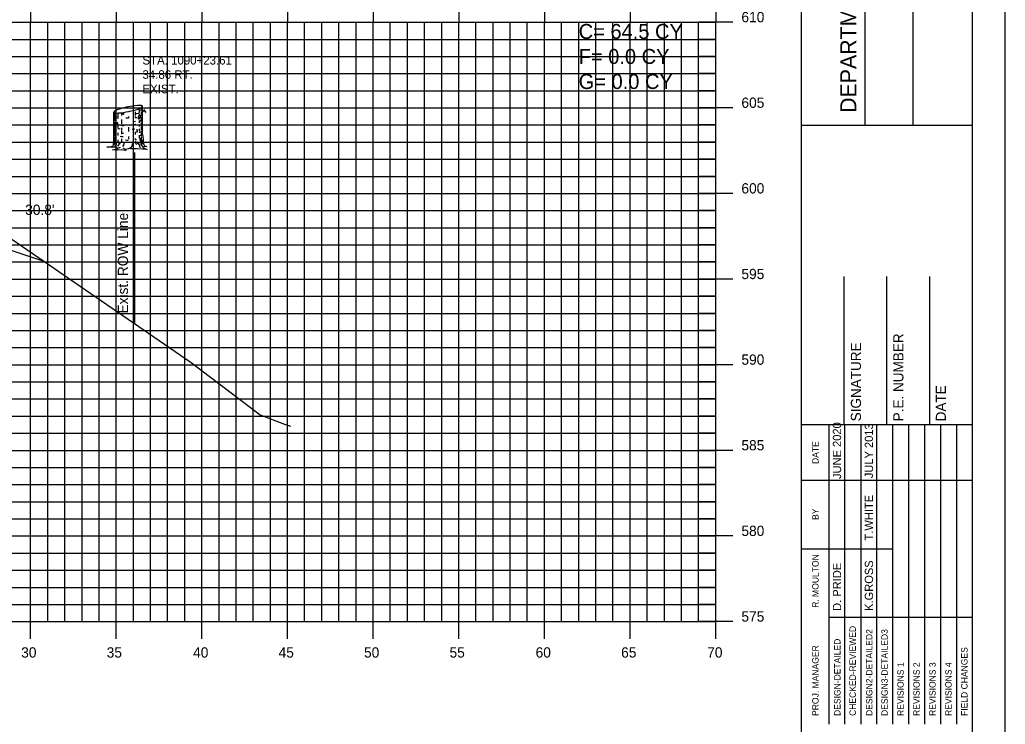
# Model space of a CAD drawing. Extents: x 1073421 to 1073591, y 779716 to 779826.
# Drawn here: x 1073533.3 to 1073590.9, y 779763.7 to 779804.9 of the extents above; entities that cross this region are included whole.
import ezdxf

# ---------------------------------------------------------------- set-up
doc = ezdxf.new("R2010")
doc.units = 0
for name, color, linetype in [('BORDER', 7, 'Continuous'), ('D_Roadway_Centerline', 7, 'Continuous'), ('D_Text_Monospaced', 7, 'Continuous'), ('D_Text_Standard', 7, 'Continuous'), ('E_ROW_Line', 7, 'Continuous'), ('H_V ANNOTATION', 7, 'Continuous'), ('M_Trees_Conifer_Pay', 7, 'Continuous'), ('MAJOR', 7, 'Continuous'), ('MINOR', 7, 'Continuous'), ('PLOT BOUNDARY', 7, 'Continuous'), ('S_Roadway_Centerline', 7, 'Continuous'), ('S_Trees_Decid_Pay', 7, 'Continuous')]:
    doc.layers.add(name, color=color, linetype=linetype)

msp = doc.modelspace()

# ---------------------------------------------------------------- linework, layer by layer
at = {"layer": 'BORDER'}
for p, q in [((1073578.959, 779718.706), (1073578.959, 779823.706)), ((1073582.688, 779798.703), (1073582.688, 779823.703)), ((1073585.483, 779798.703), (1073585.483, 779823.703)), ((1073578.96, 779798.7), (1073588.959, 779798.7)), ((1073581.459, 779781.209), (1073581.459, 779789.856)), ((1073583.959, 779781.209), (1073583.959, 779789.856)), ((1073586.459, 779781.209), (1073586.459, 779789.856)), ((1073578.959, 779781.209), (1073588.959, 779781.209))]:
    msp.add_line(p, q, dxfattribs=at)
msp.add_lwpolyline([(1073428.959, 779718.706), (1073588.959, 779718.706), (1073588.959, 779823.706), (1073428.959, 779823.706)], close=True, dxfattribs=at)
for points in [[(1073580.574, 779777.959), (1073580.574, 779781.209)], [(1073581.507, 779763.712), (1073581.507, 779781.209)], [(1073582.439, 779781.209), (1073582.439, 779763.712)], [(1073583.37, 779763.712), (1073583.37, 779781.209)], [(1073584.302, 779763.712), (1073584.302, 779781.209)], [(1073585.234, 779763.712), (1073585.234, 779781.209)], [(1073586.165, 779763.712), (1073586.165, 779781.209)], [(1073587.097, 779763.712), (1073587.097, 779781.209)], [(1073588.029, 779763.712), (1073588.029, 779781.209)], [(1073580.575, 779763.712), (1073580.575, 779780.503)], [(1073578.959, 779777.959), (1073588.959, 779777.959)], [(1073578.959, 779773.959), (1073580.575, 779773.959)], [(1073580.574, 779773.959), (1073584.301, 779773.959)], [(1073580.574, 779769.959), (1073588.959, 779769.959)]]:
    msp.add_lwpolyline(points, dxfattribs=at)
at = {"layer": 'D_Roadway_Centerline'}
msp.add_lwpolyline([(1073529.418, 779792.528), (1073534.736, 779790.755)], dxfattribs=at)
at = {"layer": 'E_ROW_Line'}
msp.add_line((1073540.047, 779787.094), (1073540.047, 779797.094), dxfattribs=at)
msp.add_line((1073540.047, 779787.094), (1073540.047, 779797.094), dxfattribs=at)
at = {"layer": 'M_Trees_Conifer_Pay'}
for p, q in [((1073538.822, 779797.738), (1073538.822, 779799.46)), ((1073540.069, 779799.466), (1073540.069, 779799.266)), ((1073540.297, 779799.662), (1073540.297, 779799.439)), ((1073540.414, 779799.723), (1073540.414, 779799.56)), ((1073540.414, 779799.493), (1073540.414, 779799.365)), ((1073540.486, 779798.148), (1073540.486, 779799.795)), ((1073538.869, 779799.423), (1073538.869, 779798.951)), ((1073538.869, 779798.887), (1073538.869, 779798.579)), ((1073538.927, 779799.411), (1073538.927, 779799.314)), ((1073538.927, 779799.239), (1073538.927, 779799.035)), ((1073538.927, 779798.978), (1073538.927, 779798.778)), ((1073539.053, 779799.404), (1073539.053, 779799.171)), ((1073539.053, 779799.131), (1073539.053, 779799.056)), ((1073539.273, 779799.424), (1073539.273, 779799.256)), ((1073539.273, 779799.019), (1073539.273, 779798.782)), ((1073539.678, 779799.192), (1073539.678, 779799.097)), ((1073540.069, 779799.209), (1073540.069, 779799.12)), ((1073540.297, 779799.35), (1073540.297, 779799.303)), ((1073540.297, 779798.968), (1073540.297, 779798.836)), ((1073540.354, 779799.167), (1073540.303, 779799.108)), ((1073540.414, 779799.178), (1073540.414, 779798.842)), ((1073538.869, 779798.531), (1073538.869, 779798.039)), ((1073538.927, 779798.731), (1073538.927, 779798.395)), ((1073538.927, 779798.342), (1073538.927, 779798.206)), ((1073539.053, 779798.653), (1073539.053, 779798.514)), ((1073539.273, 779798.537), (1073539.273, 779798.385)), ((1073539.273, 779798.342), (1073539.273, 779798.169)), ((1073539.678, 779798.579), (1073539.678, 779798.505)), ((1073539.678, 779798.48), (1073539.678, 779798.331)), ((1073540.069, 779798.772), (1073540.069, 779798.667)), ((1073540.069, 779798.301), (1073540.069, 779798.154)), ((1073540.297, 779798.725), (1073540.297, 779798.615)), ((1073540.297, 779798.48), (1073540.297, 779798.338)), ((1073540.414, 779798.805), (1073540.414, 779798.642)), ((1073540.414, 779798.595), (1073540.414, 779798.379)), ((1073540.414, 779798.348), (1073540.414, 779798.274)), ((1073538.869, 779797.986), (1073538.869, 779797.738)), ((1073538.927, 779798.107), (1073538.927, 779797.728)), ((1073539.053, 779798.243), (1073539.053, 779798.101)), ((1073539.053, 779797.839), (1073539.053, 779797.745)), ((1073539.273, 779797.891), (1073539.273, 779797.738)), ((1073539.678, 779798.039), (1073539.678, 779797.886)), ((1073540.069, 779797.922), (1073540.069, 779797.833)), ((1073540.297, 779798.111), (1073540.297, 779797.938)), ((1073540.414, 779798.233), (1073540.414, 779798.06)), ((1073539.053, 779797.345), (1073539.216, 779797.409)), ((1073539.49, 779797.281), (1073539.364, 779797.345))]:
    msp.add_line(p, q, dxfattribs=at)
for points in [[(1073540.303, 779799.293), (1073540.34, 779799.219), (1073540.387, 779799.276), (1073540.445, 779799.344), (1073540.537, 779799.538), (1073540.601, 779799.585), (1073540.632, 779799.592)], [(1073540.317, 779799.04), (1073540.354, 779799.167), (1073540.418, 779799.283), (1073540.448, 779799.35), (1073540.517, 779799.497)], [(1073540.532, 779799.526), (1073540.607, 779799.534), (1073540.679, 779799.435)], [(1073539.001, 779798.766), (1073538.995, 779798.861), (1073539.038, 779798.838), (1073539.038, 779798.743)], [(1073540.269, 779799.256), (1073540.238, 779799.171), (1073540.235, 779799.104), (1073540.265, 779799.04)], [(1073540.14, 779798.367), (1073540.153, 779798.29), (1073540.2, 779798.301), (1073540.187, 779798.467)], [(1073540.486, 779798.148), (1073540.537, 779797.886), (1073540.553, 779797.613), (1073540.611, 779797.488), (1073540.747, 779797.457), (1073540.517, 779797.419), (1073540.517, 779797.419), (1073540.523, 779797.372), (1073540.77, 779797.278), (1073540.496, 779797.294), (1073540.14, 779797.314), (1073539.819, 779797.304), (1073539.825, 779797.386), (1073539.677, 779797.304), (1073539.49, 779797.281), (1073539.514, 779797.213), (1073539.246, 779797.257), (1073539.026, 779797.23), (1073538.733, 779797.247), (1073539.022, 779797.304), (1073539.053, 779797.345), (1073538.89, 779797.403), (1073538.653, 779797.413), (1073538.412, 779797.413), (1073538.754, 779797.471), (1073538.796, 779797.551), (1073538.822, 779797.738)], [(1073540.076, 779797.755), (1073540.086, 779797.629), (1073540.16, 779797.586)], [(1073540.313, 779797.86), (1073540.387, 779797.755), (1073540.391, 779797.582), (1073540.517, 779797.419)], [(1073540.412, 779798.006), (1073540.418, 779797.86), (1073540.465, 779797.792), (1073540.475, 779797.593)], [(1073538.87, 779797.691), (1073538.849, 779797.613), (1073538.828, 779797.518)], [(1073538.948, 779797.671), (1073538.954, 779797.555), (1073538.901, 779797.467), (1073538.89, 779797.403)], [(1073539.111, 779797.698), (1073539.111, 779797.566), (1073539.022, 779797.467)], [(1073539.337, 779797.457), (1073539.404, 779797.551), (1073539.431, 779797.691)], [(1073539.825, 779797.386), (1073539.899, 779797.528), (1073539.909, 779797.629)], [(1073540.354, 779797.366), (1073540.34, 779797.504), (1073540.265, 779797.633)]]:
    msp.add_lwpolyline(points, dxfattribs=at)
for centre, radius, start, end in [((1073540.155, 779800.109), 0.571, 284.43166, 292.41325), ((1073539.153, 779799.51), 0.571, 240, 247.05866), ((1073539.152, 779799.721), 0.571, 246.85973, 257.98457), ((1073539.654, 779803.472), 4.124, 264.6955, 266.73309), ((1073539.654, 779803.028), 4.124, 273.70524, 275.95043), ((1073539.653, 779803.239), 4.124, 275.78493, 277.05584), ((1073540.155, 779799.51), 0.571, 284.44928, 297.04285), ((1073540.453, 779799.071), 0.0334, 343.94846, 354.21506), ((1073539.653, 779802.792), 4.124, 264.08098, 266.66759), ((1073539.653, 779802.582), 4.124, 270, 270.35814), ((1073539.653, 779802.582), 4.124, 273.14934, 275.45691), ((1073540.153, 779798.828), 0.571, 285.39827, 297.18959), ((1073538.854, 779798.19), 0.0334, 163.94846, 180), ((1073539.141, 779798.636), 0.571, 241.23686, 248.02677), ((1073539.653, 779802.148), 4.124, 263.49906, 265.83975), ((1073539.653, 779802.345), 4.124, 264.71603, 266.31934), ((1073539.653, 779801.952), 4.124, 275.78493, 276.78961), ((1073540.153, 779798.435), 0.571, 288.50673, 297.27208), ((1073539.653, 779801.732), 4.124, 262.44379, 263.51202)]:
    msp.add_arc(centre, radius, start, end, dxfattribs=at)
at = {"layer": 'MAJOR'}
for p, q in [((1073533.959, 779805.708), (1073533.959, 779804.706)), ((1073538.959, 779805.708), (1073538.959, 779804.706)), ((1073543.959, 779805.708), (1073543.959, 779804.706)), ((1073548.959, 779805.708), (1073548.959, 779804.706)), ((1073553.959, 779805.708), (1073553.959, 779804.706)), ((1073558.959, 779805.708), (1073558.959, 779804.706)), ((1073563.959, 779805.708), (1073563.959, 779804.706)), ((1073568.959, 779805.708), (1073568.959, 779804.706)), ((1073573.959, 779805.708), (1073573.959, 779804.706)), ((1073433.959, 779804.706), (1073573.959, 779804.706)), ((1073433.959, 779804.706), (1073573.959, 779804.706)), ((1073533.959, 779769.706), (1073533.959, 779804.706)), ((1073538.959, 779769.706), (1073538.959, 779804.706)), ((1073543.959, 779769.706), (1073543.959, 779804.706)), ((1073548.959, 779769.706), (1073548.959, 779804.706)), ((1073553.959, 779769.706), (1073553.959, 779804.706)), ((1073558.959, 779769.706), (1073558.959, 779804.706)), ((1073563.959, 779769.706), (1073563.959, 779804.706)), ((1073568.959, 779769.706), (1073568.959, 779804.706)), ((1073574.961, 779804.706), (1073572.957, 779804.706)), ((1073573.959, 779769.706), (1073573.959, 779804.706)), ((1073573.959, 779769.706), (1073573.959, 779804.706)), ((1073433.959, 779799.706), (1073573.959, 779799.706)), ((1073574.961, 779799.706), (1073572.957, 779799.706)), ((1073433.959, 779794.706), (1073573.959, 779794.706)), ((1073574.961, 779794.706), (1073572.957, 779794.706)), ((1073433.959, 779789.706), (1073573.959, 779789.706)), ((1073574.961, 779789.706), (1073572.957, 779789.706)), ((1073433.959, 779784.706), (1073573.959, 779784.706)), ((1073574.961, 779784.706), (1073572.957, 779784.706)), ((1073433.959, 779779.706), (1073573.959, 779779.706)), ((1073574.961, 779779.706), (1073572.957, 779779.706)), ((1073433.959, 779774.706), (1073573.959, 779774.706)), ((1073574.961, 779774.706), (1073572.957, 779774.706)), ((1073433.959, 779769.706), (1073573.959, 779769.706)), ((1073433.959, 779769.706), (1073573.959, 779769.706)), ((1073533.959, 779768.704), (1073533.959, 779769.706)), ((1073538.959, 779768.704), (1073538.959, 779769.706)), ((1073543.959, 779768.704), (1073543.959, 779769.706)), ((1073548.959, 779768.704), (1073548.959, 779769.706)), ((1073553.959, 779768.704), (1073553.959, 779769.706)), ((1073558.959, 779768.704), (1073558.959, 779769.706)), ((1073563.959, 779768.704), (1073563.959, 779769.706)), ((1073568.959, 779768.704), (1073568.959, 779769.706)), ((1073574.961, 779769.706), (1073572.957, 779769.706)), ((1073573.959, 779768.704), (1073573.959, 779769.706))]:
    msp.add_line(p, q, dxfattribs=at)
at = {"layer": 'MINOR'}
for p, q in [((1073534.959, 779769.706), (1073534.959, 779804.706)), ((1073535.959, 779769.706), (1073535.959, 779804.706)), ((1073536.959, 779769.706), (1073536.959, 779804.706)), ((1073537.959, 779769.706), (1073537.959, 779804.706)), ((1073539.959, 779769.706), (1073539.959, 779804.706)), ((1073540.959, 779769.706), (1073540.959, 779804.706)), ((1073541.959, 779769.706), (1073541.959, 779804.706)), ((1073542.959, 779769.706), (1073542.959, 779804.706)), ((1073544.959, 779769.706), (1073544.959, 779804.706)), ((1073545.959, 779769.706), (1073545.959, 779804.706)), ((1073546.959, 779769.706), (1073546.959, 779804.706)), ((1073547.959, 779769.706), (1073547.959, 779804.706)), ((1073549.959, 779769.706), (1073549.959, 779804.706)), ((1073550.959, 779769.706), (1073550.959, 779804.706)), ((1073551.959, 779769.706), (1073551.959, 779804.706)), ((1073552.959, 779769.706), (1073552.959, 779804.706)), ((1073554.959, 779769.706), (1073554.959, 779804.706)), ((1073555.959, 779769.706), (1073555.959, 779804.706)), ((1073556.959, 779769.706), (1073556.959, 779804.706)), ((1073557.959, 779769.706), (1073557.959, 779804.706)), ((1073559.959, 779769.706), (1073559.959, 779804.706)), ((1073560.959, 779769.706), (1073560.959, 779804.706)), ((1073561.959, 779769.706), (1073561.959, 779804.706)), ((1073562.959, 779769.706), (1073562.959, 779804.706)), ((1073564.959, 779769.706), (1073564.959, 779804.706)), ((1073565.959, 779769.706), (1073565.959, 779804.706)), ((1073566.959, 779769.706), (1073566.959, 779804.706)), ((1073567.959, 779769.706), (1073567.959, 779804.706)), ((1073569.959, 779769.706), (1073569.959, 779804.706)), ((1073570.959, 779769.706), (1073570.959, 779804.706)), ((1073571.959, 779769.706), (1073571.959, 779804.706)), ((1073572.959, 779769.706), (1073572.959, 779804.706)), ((1073433.959, 779803.706), (1073573.959, 779803.706)), ((1073573.959, 779803.706), (1073572.957, 779803.706)), ((1073433.959, 779802.706), (1073573.959, 779802.706)), ((1073573.959, 779802.706), (1073572.957, 779802.706)), ((1073433.959, 779801.706), (1073573.959, 779801.706)), ((1073573.959, 779801.706), (1073572.957, 779801.706)), ((1073433.959, 779800.706), (1073573.959, 779800.706)), ((1073573.959, 779800.706), (1073572.957, 779800.706)), ((1073433.959, 779798.706), (1073573.959, 779798.706)), ((1073573.959, 779798.706), (1073572.957, 779798.706)), ((1073433.959, 779797.706), (1073573.959, 779797.706)), ((1073573.959, 779797.706), (1073572.957, 779797.706)), ((1073433.959, 779796.706), (1073573.959, 779796.706)), ((1073573.959, 779796.706), (1073572.957, 779796.706)), ((1073433.959, 779795.706), (1073573.959, 779795.706)), ((1073573.959, 779795.706), (1073572.957, 779795.706)), ((1073433.959, 779793.706), (1073573.959, 779793.706)), ((1073573.959, 779793.706), (1073572.957, 779793.706)), ((1073433.959, 779792.706), (1073573.959, 779792.706)), ((1073573.959, 779792.706), (1073572.957, 779792.706)), ((1073433.959, 779791.706), (1073573.959, 779791.706)), ((1073573.959, 779791.706), (1073572.957, 779791.706)), ((1073433.959, 779790.706), (1073573.959, 779790.706)), ((1073573.959, 779790.706), (1073572.957, 779790.706)), ((1073433.959, 779788.706), (1073573.959, 779788.706)), ((1073573.959, 779788.706), (1073572.957, 779788.706)), ((1073433.959, 779787.706), (1073573.959, 779787.706)), ((1073573.959, 779787.706), (1073572.957, 779787.706)), ((1073433.959, 779786.706), (1073573.959, 779786.706)), ((1073573.959, 779786.706), (1073572.957, 779786.706)), ((1073433.959, 779785.706), (1073573.959, 779785.706)), ((1073573.959, 779785.706), (1073572.957, 779785.706)), ((1073433.959, 779783.706), (1073573.959, 779783.706)), ((1073573.959, 779783.706), (1073572.957, 779783.706)), ((1073433.959, 779782.706), (1073573.959, 779782.706)), ((1073573.959, 779782.706), (1073572.957, 779782.706)), ((1073433.959, 779781.706), (1073573.959, 779781.706)), ((1073573.959, 779781.706), (1073572.957, 779781.706)), ((1073433.959, 779780.706), (1073573.959, 779780.706)), ((1073573.959, 779780.706), (1073572.957, 779780.706)), ((1073433.959, 779778.706), (1073573.959, 779778.706)), ((1073573.959, 779778.706), (1073572.957, 779778.706)), ((1073433.959, 779777.706), (1073573.959, 779777.706)), ((1073573.959, 779777.706), (1073572.957, 779777.706)), ((1073433.959, 779776.706), (1073573.959, 779776.706)), ((1073573.959, 779776.706), (1073572.957, 779776.706)), ((1073433.959, 779775.706), (1073573.959, 779775.706)), ((1073573.959, 779775.706), (1073572.957, 779775.706)), ((1073433.959, 779773.706), (1073573.959, 779773.706)), ((1073573.959, 779773.706), (1073572.957, 779773.706)), ((1073433.959, 779772.706), (1073573.959, 779772.706)), ((1073573.959, 779772.706), (1073572.957, 779772.706)), ((1073433.959, 779771.706), (1073573.959, 779771.706)), ((1073573.959, 779771.706), (1073572.957, 779771.706)), ((1073433.959, 779770.706), (1073573.959, 779770.706)), ((1073573.959, 779770.706), (1073572.957, 779770.706))]:
    msp.add_line(p, q, dxfattribs=at)
at = {"layer": 'PLOT BOUNDARY'}
msp.add_lwpolyline([(1073420.866, 779715.646), (1073590.866, 779715.646), (1073590.866, 779825.646), (1073420.866, 779825.646)], close=True, dxfattribs=at)
at = {"layer": 'S_Roadway_Centerline'}
msp.add_lwpolyline([(1073532.866, 779792.044), (1073543.324, 779784.835), (1073547.369, 779781.776), (1073548.784, 779781.239), (1073549.129, 779781.121)], dxfattribs=at)
at = {"layer": 'S_Trees_Decid_Pay'}
for centre, radius, start, end in [((1073538.853, 779799.459), 0.0314, 156.51582, 169.2194), ((1073538.848, 779799.46), 0.0264, 169.2194, 180.03145), ((1073538.845, 779799.46), 0.0226, 180.03145, 191.7194), ((1073538.845, 779799.46), 0.0226, 191.7194, 203.40735), ((1073538.873, 779799.45), 0.0527, 146.7194, 156.51582), ((1073538.848, 779799.461), 0.0264, 203.40735, 214.2194), ((1073538.852, 779799.464), 0.0314, 214.2194, 226.92298), ((1073538.897, 779799.434), 0.0817, 132.38868, 146.7194), ((1073538.867, 779799.48), 0.0527, 226.92298, 236.7194), ((1073538.883, 779799.504), 0.0817, 236.7194, 251.05013), ((1073539.011, 779799.31), 0.251, 124.2194, 132.38868), ((1073539.321, 779798.854), 0.802, 108.05939, 124.2194), ((1073540.678, 779794.692), 5.179, 101.7194, 108.05939), ((1073538.63, 779804.563), 5.179, 275.37941, 281.7194), ((1073540.678, 779794.692), 5.179, 95.37941, 101.7194), ((1073538.63, 779804.563), 5.179, 281.7194, 288.05939), ((1073540.267, 779799.05), 0.802, 79.2194, 95.37941), ((1073539.987, 779800.401), 0.802, 288.05939, 304.2194), ((1073540.155, 779799.954), 0.571, 297.0237, 300), ((1073540.37, 779799.592), 0.251, 71.05013, 79.2194), ((1073540.297, 779799.946), 0.251, 304.2194, 312.38868), ((1073540.354, 779799.764), 0.172, 300, 311.25059), ((1073540.354, 779799.609), 0.172, 300, 311.25059), ((1073540.425, 779799.751), 0.0817, 56.7194, 71.05013), ((1073540.411, 779799.821), 0.0817, 312.38868, 326.7194), ((1073540.427, 779799.681), 0.0624, 311.25059, 330), ((1073540.427, 779799.527), 0.0624, 311.25059, 330), ((1073540.441, 779799.776), 0.0527, 46.92298, 56.7194), ((1073540.456, 779799.791), 0.0314, 34.2194, 46.92298), ((1073540.435, 779799.805), 0.0527, 326.7194, 336.51582), ((1073540.442, 779799.672), 0.0441, 330, 343.94846), ((1073540.442, 779799.518), 0.0441, 330, 343.94846), ((1073540.46, 779799.794), 0.0264, 23.40735, 34.2194), ((1073540.455, 779799.796), 0.0314, 336.51582, 349.2194), ((1073540.463, 779799.795), 0.0226, 11.7194, 23.40735), ((1073540.463, 779799.795), 0.0226, 0.03145, 11.7194), ((1073540.46, 779799.795), 0.0264, 349.2194, 0.03145), ((1073540.453, 779799.669), 0.0334, 343.94846, 354.21506), ((1073540.453, 779799.515), 0.0334, 343.94846, 354.21506), ((1073538.854, 779799.282), 0.0334, 163.94846, 180), ((1073538.854, 779799.282), 0.0334, 180, 196.05154), ((1073538.864, 779799.285), 0.0441, 196.05154, 210), ((1073538.88, 779799.294), 0.0624, 210, 228.74941), ((1073538.953, 779799.376), 0.172, 228.74941, 240), ((1073538.937, 779799.664), 0.251, 251.05013, 259.2194), ((1073539.152, 779799.721), 0.571, 240, 240.33672), ((1073539.041, 779800.205), 0.802, 259.2194, 275.37941), ((1073539.653, 779803.239), 4.124, 268.07512, 270), ((1073539.653, 779803.239), 4.124, 270, 270.35814), ((1073539.654, 779803.472), 4.124, 276.23804, 278.1032), ((1073540.155, 779799.954), 0.571, 278.1032, 284.36665), ((1073538.854, 779798.835), 0.0334, 163.94846, 180), ((1073538.854, 779798.835), 0.0334, 180, 196.05154), ((1073538.854, 779798.625), 0.0334, 163.94846, 180), ((1073538.854, 779798.625), 0.0334, 180, 196.05154), ((1073538.854, 779798.388), 0.0334, 163.94846, 180), ((1073538.854, 779798.388), 0.0334, 180, 196.05154), ((1073538.864, 779798.838), 0.0441, 196.05154, 210), ((1073538.864, 779798.628), 0.0441, 196.05154, 210), ((1073538.864, 779798.391), 0.0441, 196.05154, 210), ((1073538.88, 779798.847), 0.0624, 210, 228.74941), ((1073538.88, 779798.637), 0.0624, 210, 228.74941), ((1073538.88, 779798.4), 0.0624, 210, 228.74941), ((1073538.953, 779798.93), 0.172, 228.74941, 240), ((1073538.953, 779798.72), 0.172, 228.74941, 240), ((1073538.953, 779798.483), 0.172, 228.74941, 240), ((1073539.152, 779799.275), 0.571, 240, 240.33672), ((1073539.152, 779799.065), 0.571, 240, 246.85973), ((1073539.152, 779798.828), 0.571, 240, 246.85973), ((1073539.152, 779799.065), 0.571, 259.27072, 261.8968), ((1073539.653, 779802.582), 4.124, 261.8968, 263.14738), ((1073539.653, 779802.792), 4.124, 277.61247, 278.1032), ((1073540.153, 779799.275), 0.571, 278.1032, 286.92962), ((1073540.153, 779799.275), 0.571, 297.18959, 300), ((1073540.153, 779799.065), 0.571, 297.18959, 300), ((1073540.353, 779798.93), 0.172, 300, 311.25059), ((1073540.353, 779798.72), 0.172, 300, 311.25059), ((1073540.425, 779798.847), 0.0624, 311.25059, 330), ((1073540.425, 779798.637), 0.0624, 311.25059, 330), ((1073540.441, 779798.838), 0.0441, 330, 343.94846), ((1073540.441, 779798.628), 0.0441, 330, 343.94846), ((1073540.451, 779798.835), 0.0334, 343.94846, 354.21506), ((1073540.451, 779798.625), 0.0334, 343.94846, 354.21506), ((1073538.854, 779797.995), 0.0334, 163.94846, 180), ((1073538.854, 779797.995), 0.0334, 180, 196.05154), ((1073538.854, 779797.775), 0.0334, 163.94846, 180), ((1073538.854, 779797.775), 0.0334, 180, 196.05154), ((1073538.864, 779797.998), 0.0441, 196.05154, 210), ((1073538.864, 779797.778), 0.0441, 196.05154, 210), ((1073538.88, 779798.007), 0.0624, 210, 228.74941), ((1073538.88, 779797.787), 0.0624, 210, 228.74941), ((1073538.953, 779798.09), 0.172, 228.74941, 240), ((1073538.953, 779797.869), 0.172, 228.74941, 240), ((1073539.152, 779798.435), 0.571, 240, 246.85973), ((1073539.152, 779798.214), 0.571, 240, 244.53138), ((1073539.653, 779801.952), 4.124, 267.81166, 270), ((1073539.653, 779801.952), 4.124, 270, 270.13279), ((1073540.153, 779798.63), 0.571, 289.29072, 300), ((1073540.353, 779798.285), 0.172, 300, 311.25059), ((1073540.353, 779797.869), 0.172, 300, 311.25059), ((1073540.425, 779798.203), 0.0624, 311.25059, 330), ((1073540.425, 779797.787), 0.0624, 311.25059, 330), ((1073540.441, 779798.193), 0.0441, 330, 343.94846), ((1073540.441, 779797.778), 0.0441, 330, 343.94846), ((1073540.451, 779798.19), 0.0334, 343.94846, 354.21506), ((1073540.451, 779797.775), 0.0334, 343.94846, 354.21506), ((1073539.653, 779801.732), 4.124, 277.36842, 278.1032), ((1073540.153, 779798.214), 0.571, 278.1032, 281.63703)]:
    msp.add_arc(centre, radius, start, end, dxfattribs=at)

# ---------------------------------------------------------------- texts
at = {"layer": 'BORDER'}
for s, height, p in [('DEPARTMENT OF TRANSPORTATION', 0.93176, (1073582.166, 779799.412)), ('DEPARTMENT OF TRANSPORTATION', 0.93176, (1073582.166, 779799.412)), ('P.E. NUMBER', 0.59055, (1073584.92, 779781.401)), ('SIGNATURE', 0.5906, (1073582.44, 779781.401)), ('DATE', 0.5906, (1073587.4, 779781.401)), ('JUNE 2020', 0.4845, (1073581.282, 779778.034)), ('JULY 2013', 0.4845, (1073583.146, 779778.08)), ('DATE', 0.3714, (1073579.964, 779778.914)), ('T.WHITE', 0.4845, (1073583.146, 779774.444)), ('BY', 0.3714, (1073579.964, 779775.644)), ('R. MOULTON', 0.3727, (1073579.964, 779770.511)), ('D. PRIDE', 0.4845, (1073581.282, 779770.332)), ('K.GROSS', 0.4845, (1073583.146, 779770.332)), ('CHECKED-REVIEWED', 0.37275, (1073582.14, 779764.197)), ('DESIGN2-DETAILED2', 0.37275, (1073583.109, 779764.197)), ('DESIGN3-DETAILED3', 0.37275, (1073584.004, 779764.197)), ('DESIGN-DETAILED', 0.37275, (1073581.246, 779764.197)), ('PROJ. MANAGER', 0.37275, (1073579.964, 779764.197)), ('FIELD CHANGES', 0.37275, (1073588.662, 779764.197)), ('REVISIONS 1', 0.37275, (1073584.935, 779764.197)), ('REVISIONS 2', 0.37275, (1073585.867, 779764.197)), ('REVISIONS 3', 0.37275, (1073586.799, 779764.197)), ('REVISIONS 4', 0.37275, (1073587.73, 779764.197))]:
    msp.add_text(s, height=height, rotation=90, dxfattribs=at).set_placement(p)
at = {"layer": 'D_Text_Monospaced'}
for s, height, p in [('STA. 1090+23.61', 0.49998, (1073540.489, 779802.236)), ('34.86 RT.', 0.5, (1073540.489, 779801.402)), ('EXIST. ', 0.5, (1073540.489, 779800.562))]:
    msp.add_text(s, height=height, dxfattribs=at).set_placement(p)
at = {"layer": 'D_Text_Standard'}
msp.add_text("30.8'", height=0.6, dxfattribs=at).set_placement((1073533.642, 779793.455))
at = {"layer": 'E_ROW_Line'}
msp.add_text('Exist. ROW Line', height=0.6, rotation=90, dxfattribs=at).set_placement((1073539.647, 779787.694))
at = {"layer": 'H_V ANNOTATION'}
for s, height, p in [('610', 0.6, (1073575.459, 779804.706)), ('C= 64.5 CY', 0.875, (1073565.959, 779803.731)), ('F= 0.0 CY', 0.875, (1073565.959, 779802.269)), ('G= 0.0 CY', 0.875, (1073565.959, 779800.808)), ('605', 0.6, (1073575.459, 779799.706)), ('600', 0.6, (1073575.459, 779794.706)), ('595', 0.6, (1073575.459, 779789.706)), ('590', 0.6, (1073575.459, 779784.706)), ('585', 0.6, (1073575.459, 779779.706)), ('580', 0.6, (1073575.459, 779774.706)), ('575', 0.6, (1073575.459, 779769.706)), ('30', 0.6, (1073533.408, 779767.606)), ('35', 0.6, (1073538.4, 779767.606)), ('40', 0.6, (1073543.445, 779767.606)), ('45', 0.6, (1073548.437, 779767.606)), ('50', 0.6, (1073553.424, 779767.606)), ('55', 0.6, (1073558.416, 779767.606)), ('60', 0.6, (1073563.445, 779767.606)), ('65', 0.6, (1073568.437, 779767.606)), ('70', 0.6, (1073573.461, 779767.606))]:
    msp.add_text(s, height=height, dxfattribs=at).set_placement(p)

doc.saveas('drawing.dxf')
